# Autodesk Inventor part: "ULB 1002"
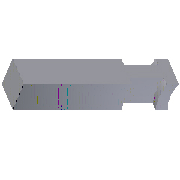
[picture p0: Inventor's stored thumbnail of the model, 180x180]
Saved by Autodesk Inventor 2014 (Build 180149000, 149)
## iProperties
Created: 2009-11
Part Number: "ULB 1002"
Material: DIN 1.2344
Description: Flat Core Blade
Document SubType Name: Modeling
Designer: gaom
Standard Revision: 1
Manufacturer: DME
Language: en-US
Size Designation: "1002"
Categories: <MemberInstance><Categories><Category DisplayName="Mold" InternalName="349578f2-f4d4-4954-8c09-8e99297a61c0" Mnemonic="MOLD"><Category DisplayName="Lifter Compo
Density: 100 g/cm^3
Appearance: Violet
IsCustomPart: 1
Author: gaom
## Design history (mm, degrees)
sketch "Sketch1"
  geometry: L1 (7.5, 0)-(7.5, -246.614); L2 (0, 0)-(0, -243.624); L3 (0, 0)-(15, 0); L4 (15, -243.624)-(15, 0); L5 (0, -250)-(0, -243.624); L6 (15, -250)-(15, -243.624); A1 r 10 centre (7.5, -256.614) between (7.5, -246.614) and (0, -250); A2 r 10 centre (7.5, -256.614) between (15, -250) and (7.5, -246.614); A3 r 15 centre (7.5, -256.614) between (15, -243.624) and (0, -243.624); A4 r 30 centre (7.5, -256.614) between (15, -227.567) and (0, -227.567); A5 r 15 centre (7.5, -256.614) between (15, -243.624) and (0, -243.624)
  constraints: 12 end point, 12 point on circle, 5 centre point, 3 coincident, 3 parallel, 2 point on line, 1 midpoint, 1 perpendicular, 1 symmetric about line, 1 vertical alignment, 1 other
  dimensions: "d8" = 10 radius of A1 (= R); "d18" = 5 radial gap between concentric circles of A2 A3 (= H_); "d19" = 15 radial gap between concentric circles of A3 A4 (= 3 x H_); "d20" = 15 diameter of L2 L1 (= t); "d21" = 250 vertical distance of L1.start L5.start (= l_); "d40" = 15 distance between parallel lines of L6 L5 (= Tmin_)
node "ULB_ULC"
feature "Sculpt4"
body "Solid1"
extrude "Extrusion1" new body sketch "Sketch1" stored distance "d22" = 15 (= w); taper "d23" = 0 deg
extrude "Extrusion2" join sketch "Sketch1" stored distance "d24" = 5 (= ULB_W1); taper "d25" = 0 deg
extrude "Extrusion3" join sketch "Sketch1" stored distance "d26" = 10 (= Wmin); taper "d27" = 0 deg
feature "Stitch Surface1" dims "d47" = 0.254 (derived)
sketch "Sketch2"
  geometry: L1 (15, 0)-(0, 0) reference; L2 (0, -15)-(0, 0) reference; L3 (0, -15)-(15, -15) reference; L4 (15, -15)-(15, 0) reference; 1 further point
body "Srf1"
body "Srf2"
body "Srf3"
body "Srf4"
extrude_surface "ExtrusionSrf1" dims "d28" = 250 (= l_), "d29" = 0
patch "Boundary Patch1" dims "d35" = 0, "d36" = 0, "d37" = 0, "d38" = 0, "d39" = 0
patch "Boundary Patch2" dims "d41" = 0, "d42" = 0, "d43" = 0, "d44" = 0, "d45" = 0
feature "Surface4"
body "Srf8"
other parameters: "w" = 15 [user parameter; used in 1 equation term], "R" = 10 [user parameter; used in 1 equation term], "H_" = 5 [user parameter; used in 2 equation terms], "t" = 15 [user parameter; used in 1 equation term], "l_" = 250 [user parameter; used in 2 equation terms], "Wmin" = 10 [user parameter; used in 1 equation term], "ULB_W1" = 5 [user parameter; used in 1 equation term], "Tmin_" = 15 [user parameter; used in 1 equation term]
